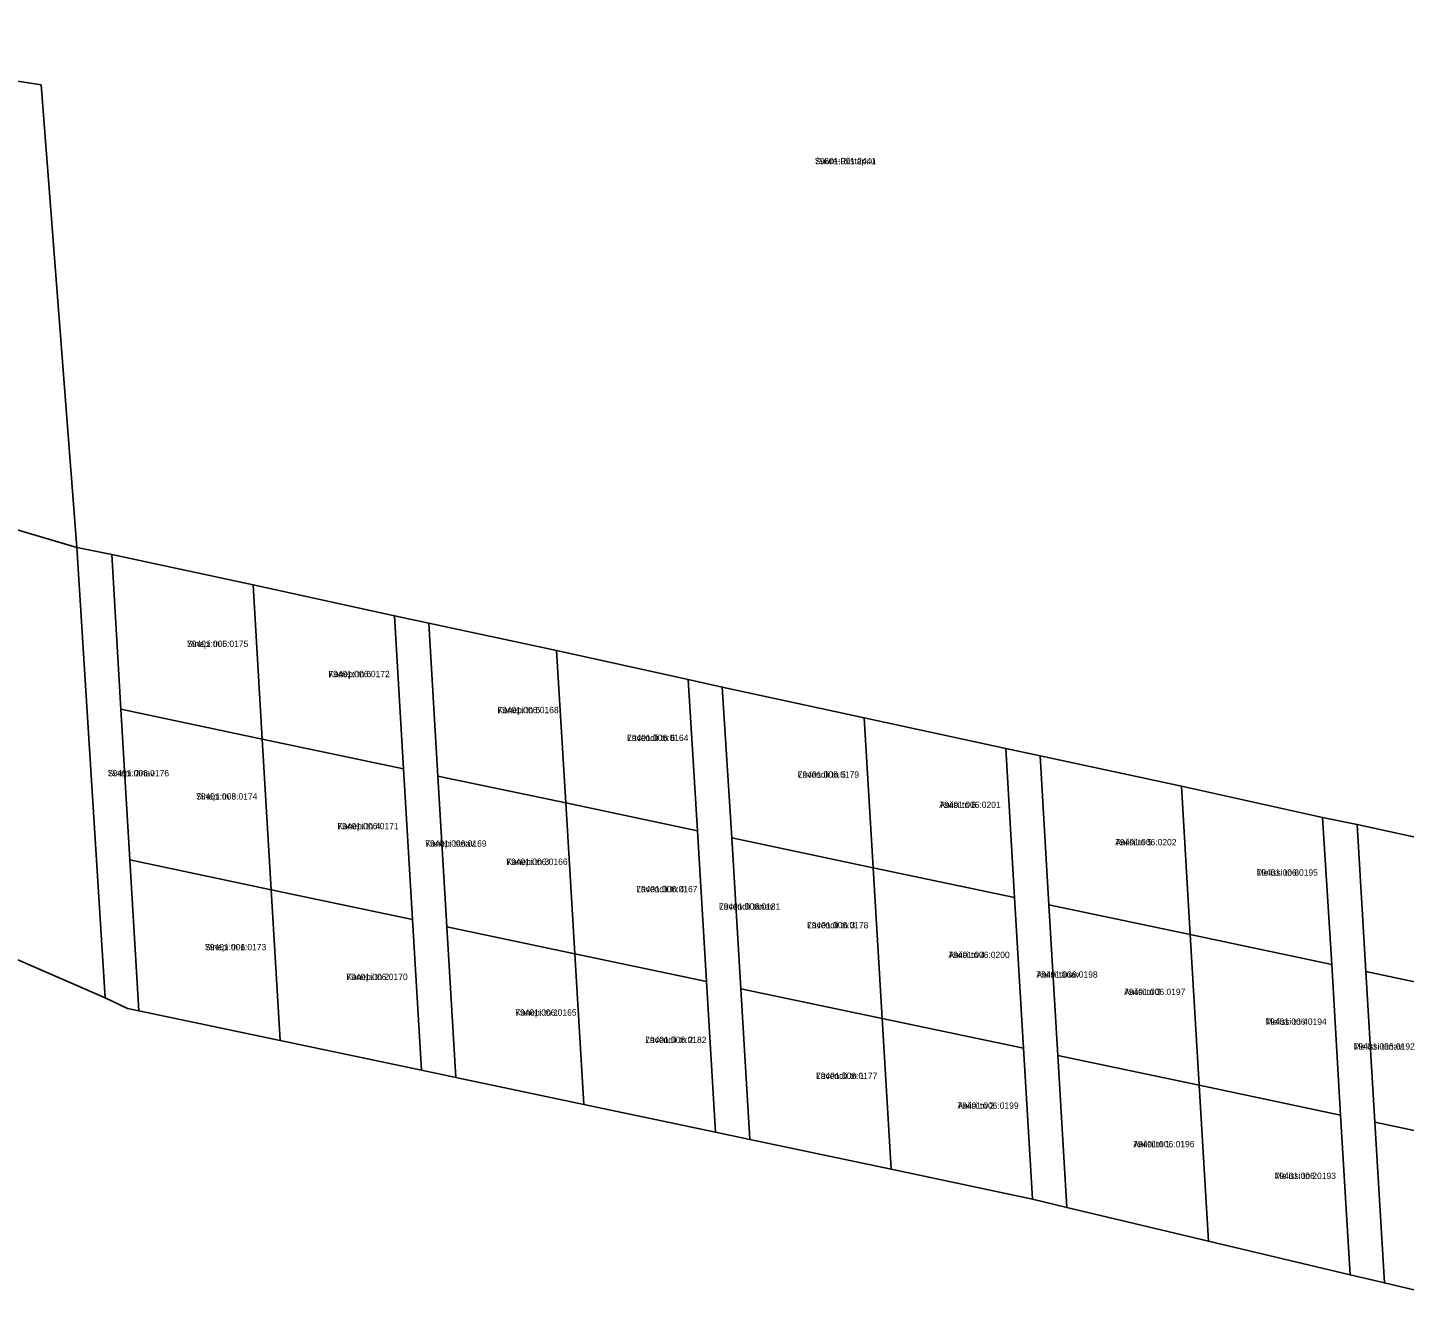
# Model space of a CAD drawing. Extents: x 625111 to 706696, y 6474150 to 6504223.
# Drawn here: x 658701.1 to 659027.1, y 6476737 to 6477042.3 of the extents above; entities that cross this region are included whole.
import ezdxf

# ---------------------------------------------------------------- set-up
doc = ezdxf.new("R2010")
doc.units = 0
for name, color, linetype in [('L_AADRESS', 7, 'Continuous'), ('PIIR', 7, 'Continuous'), ('TUNNUS', 7, 'Continuous')]:
    doc.layers.add(name, color=color, linetype=linetype)

msp = doc.modelspace()

# ---------------------------------------------------------------- linework, layer by layer
at = {"layer": 'PIIR'}
for points in [[(658616.59, 6477042.29), (658704.28, 6477028.7), (658712.75, 6476919.16), (658624.22, 6476945.38), (658602.1, 6476951.96)], [(658584.52, 6476904.86), (658594.34, 6476927.02), (658612.2, 6476918.96), (658624.22, 6476945.38), (658712.75, 6476919.16), (658719.48, 6476812.48), (658571.64, 6476876.85)], [(658712.75, 6476919.16), (658721.03, 6476917.46), (658723.2, 6476880.82), (658725.32, 6476845.12), (658727.44, 6476809.41), (658724.75, 6476809.98), (658719.48, 6476812.48)], [(658721.03, 6476917.46), (658754.52, 6476910.26), (658756.67, 6476873.77), (658723.2, 6476880.82)], [(658754.52, 6476910.26), (658788.02, 6476902.97), (658790.15, 6476866.71), (658756.67, 6476873.77)], [(658788.02, 6476902.97), (658796.14, 6476901.25), (658798.26, 6476865), (658800.39, 6476829.3), (658802.51, 6476793.59), (658794.39, 6476795.3), (658792.26, 6476831.01), (658790.15, 6476866.71)], [(658796.14, 6476901.25), (658826.37, 6476894.73), (658828.56, 6476858.62), (658798.26, 6476865)], [(658826.37, 6476894.73), (658857.54, 6476887.83), (658859.76, 6476852.04), (658828.56, 6476858.62)], [(658857.54, 6476887.83), (658865.6, 6476886.06), (658867.88, 6476850.33), (658870, 6476814.63), (658872.11, 6476778.93), (658864, 6476780.64), (658861.88, 6476816.34), (658859.76, 6476852.04)], [(658865.6, 6476886.06), (658899.18, 6476878.76), (658901.34, 6476843.28), (658867.88, 6476850.33)], [(658723.2, 6476880.82), (658756.67, 6476873.77), (658758.8, 6476838.06), (658725.32, 6476845.12)], [(658899.18, 6476878.76), (658932.74, 6476871.51), (658934.82, 6476836.22), (658901.34, 6476843.28)], [(658756.67, 6476873.77), (658790.15, 6476866.71), (658792.26, 6476831.01), (658758.8, 6476838.06)], [(658932.74, 6476871.51), (658940.85, 6476869.77), (658942.94, 6476834.51), (658945.07, 6476798.81), (658947.2, 6476762.81), (658939.07, 6476764.75), (658936.94, 6476800.52), (658934.82, 6476836.22)], [(658940.85, 6476869.77), (658974.34, 6476862.58), (658976.42, 6476827.46), (658942.94, 6476834.51)], [(658798.26, 6476865), (658828.56, 6476858.62), (658830.68, 6476822.91), (658800.39, 6476829.3)], [(658974.34, 6476862.58), (659007.74, 6476855.21), (659009.9, 6476820.4), (658976.42, 6476827.46)], [(658828.56, 6476858.62), (658859.76, 6476852.04), (658861.88, 6476816.34), (658830.68, 6476822.91)], [(659007.74, 6476855.21), (659015.92, 6476853.56), (659018.01, 6476818.69), (659020.13, 6476782.99), (659022.39, 6476744.96), (659014.26, 6476746.89), (659012.02, 6476784.7), (659009.9, 6476820.4)], [(659015.92, 6476853.56), (659049.44, 6476846.2), (659051.49, 6476811.64), (659018.01, 6476818.69)], [(658867.88, 6476850.33), (658901.34, 6476843.28), (658903.47, 6476807.57), (658870, 6476814.63)], [(658725.32, 6476845.12), (658758.8, 6476838.06), (658760.91, 6476802.36), (658727.44, 6476809.41)], [(658901.34, 6476843.28), (658934.82, 6476836.22), (658936.94, 6476800.52), (658903.47, 6476807.57)], [(658758.8, 6476838.06), (658792.26, 6476831.01), (658794.39, 6476795.3), (658760.91, 6476802.36)], [(658942.94, 6476834.51), (658976.42, 6476827.46), (658978.54, 6476791.75), (658945.07, 6476798.81)], [(658800.39, 6476829.3), (658830.68, 6476822.91), (658832.79, 6476787.21), (658802.51, 6476793.59)], [(658976.42, 6476827.46), (659009.9, 6476820.4), (659012.02, 6476784.7), (658978.54, 6476791.75)], [(658830.68, 6476822.91), (658861.88, 6476816.34), (658864, 6476780.64), (658832.79, 6476787.21)], [(659018.01, 6476818.69), (659051.49, 6476811.64), (659053.61, 6476775.93), (659020.13, 6476782.99)], [(658870, 6476814.63), (658903.47, 6476807.57), (658905.59, 6476771.87), (658872.11, 6476778.93)], [(658903.47, 6476807.57), (658936.94, 6476800.52), (658939.07, 6476764.75), (658936.46, 6476765.36), (658905.59, 6476771.87)], [(658945.07, 6476798.81), (658978.54, 6476791.75), (658980.73, 6476754.85), (658947.2, 6476762.81)], [(658978.54, 6476791.75), (659012.02, 6476784.7), (659014.26, 6476746.89), (658980.73, 6476754.85)], [(659020.13, 6476782.99), (659053.61, 6476775.93), (659055.92, 6476737), (659022.39, 6476744.96)]]:
    msp.add_lwpolyline(points, close=True, dxfattribs=at)
msp.add_lwpolyline([(659049.44, 6476846.2), (659015.92, 6476853.56), (659007.74, 6476855.21), (658974.34, 6476862.58), (658940.85, 6476869.77), (658932.74, 6476871.51), (658899.18, 6476878.76), (658865.6, 6476886.06), (658857.54, 6476887.83), (658826.37, 6476894.73), (658796.14, 6476901.25), (658788.02, 6476902.97), (658754.52, 6476910.26), (658721.03, 6476917.46), (658712.75, 6476919.16), (658704.28, 6477028.7), (658616.59, 6477042.29)], dxfattribs=at)

# ---------------------------------------------------------------- texts
at = {"layer": 'L_AADRESS'}
for s, p in [('Suure-Riistapuu', (658887.51, 6477009.92)), ('Sinepi tn 5', (658738.85, 6476895.58)), ('Kanepi tn 6', (658772.34, 6476888.42)), ('Kanepi tn 5', (658812.35, 6476879.89)), ('Lavendli tn 6', (658843.06, 6476873.3)), ('Sinepi tänav', (658720.09, 6476864.92)), ('Lavendli tn 5', (658883.47, 6476864.61)), ('Sinepi tn 3', (658741, 6476859.44)), ('Aniisi tn 6', (658917, 6476857.44)), ('Kanepi tn 4', (658774.46, 6476852.39)), ('Kanepi tänav', (658795.27, 6476848.28)), ('Aniisi tn 5', (658958.64, 6476848.58)), ('Kanepi tn 3', (658814.47, 6476843.96)), ('Melissi tn 6', (658992.12, 6476841.4)), ('Lavendli tn 4', (658845.22, 6476837.48)), ('Lavendli tänav', (658864.82, 6476833.35)), ('Lavendli tn 3', (658885.68, 6476828.95)), ('Sinepi tn 1', (658743.11, 6476823.74)), ('Aniisi tn 4', (658919.14, 6476821.9)), ('Kanepi tn 2', (658776.59, 6476816.68)), ('Aniisi tänav', (658939.97, 6476817.25)), ('Aniisi tn 3', (658960.74, 6476813.13)), ('Kanepi tn 1', (658816.59, 6476808.25)), ('Melissi tn 4', (658994.22, 6476806.08)), ('Lavendli tn 2', (658847.34, 6476801.77)), ('Melissi tänav', (659015.07, 6476800.22)), ('Lavendli tn 1', (658887.8, 6476793.25)), ('Aniisi tn 2', (658921.27, 6476786.19)), ('Aniisi tn 1', (658962.9, 6476777.07)), ('Melissi tn 2', (658996.4, 6476769.56))]:
    msp.add_text(s, height=1.5, dxfattribs=at).set_placement(p)
at = {"layer": 'TUNNUS'}
for s, p in [('79601:001:2441', (658887.51, 6477009.92)), ('79401:006:0175', (658738.85, 6476895.58)), ('79401:006:0172', (658772.34, 6476888.42)), ('79401:006:0168', (658812.35, 6476879.89)), ('79401:006:0164', (658843.06, 6476873.3)), ('79401:006:0176', (658720.09, 6476864.92)), ('79401:006:0179', (658883.47, 6476864.61)), ('79401:006:0174', (658741, 6476859.44)), ('79401:006:0201', (658917, 6476857.44)), ('79401:006:0171', (658774.46, 6476852.39)), ('79401:006:0169', (658795.27, 6476848.28)), ('79401:006:0202', (658958.64, 6476848.58)), ('79401:006:0166', (658814.47, 6476843.96)), ('79401:006:0195', (658992.12, 6476841.4)), ('79401:006:0167', (658845.22, 6476837.48)), ('79401:006:0181', (658864.82, 6476833.35)), ('79401:006:0178', (658885.68, 6476828.95)), ('79401:006:0173', (658743.11, 6476823.74)), ('79401:006:0200', (658919.14, 6476821.9)), ('79401:006:0170', (658776.59, 6476816.68)), ('79401:006:0198', (658939.97, 6476817.25)), ('79401:006:0197', (658960.74, 6476813.13)), ('79401:006:0165', (658816.59, 6476808.25)), ('79401:006:0194', (658994.22, 6476806.08)), ('79401:006:0182', (658847.34, 6476801.77)), ('79401:006:0192', (659015.07, 6476800.22)), ('79401:006:0177', (658887.8, 6476793.25)), ('79401:006:0199', (658921.27, 6476786.19)), ('79401:006:0196', (658962.9, 6476777.07)), ('79401:006:0193', (658996.4, 6476769.56))]:
    msp.add_text(s, height=1.5, dxfattribs=at).set_placement(p)

doc.saveas('drawing.dxf')
